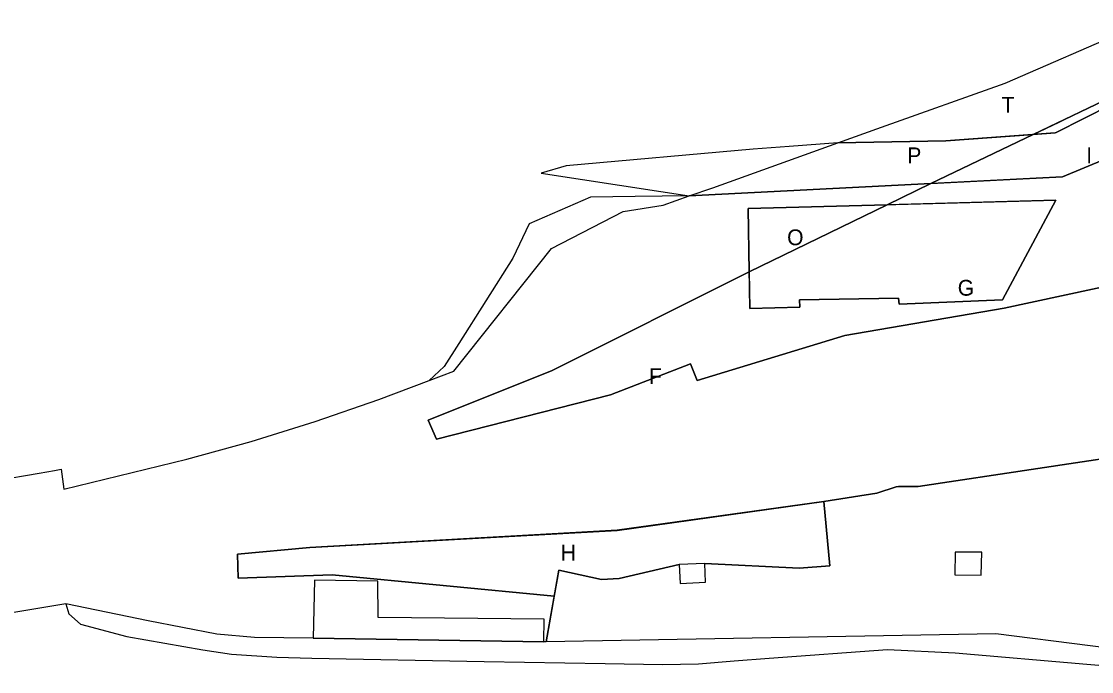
# Model space of a CAD drawing. Extents: x -749314 to -746497, y -1026537 to -1024935.
# Drawn here: x -748637.2 to -748467.6, y -1025353.9 to -1025250.8 of the extents above; entities that cross this region are included whole.
import ezdxf

# ---------------------------------------------------------------- set-up
doc = ezdxf.new("R2010")
doc.units = 0
for name, color, linetype in [('Default', 7, 'Continuous'), ('K_CD1', 7, 'Continuous'), ('K_JVL', 7, 'Continuous'), ('K_NH_SZDC', 7, 'Continuous'), ('K_SZDC1', 7, 'Continuous')]:
    doc.layers.add(name, color=color, linetype=linetype)

msp = doc.modelspace()

# ---------------------------------------------------------------- linework, layer by layer
at = {"layer": 'Default'}
for points in [[(-748507.76, -1025270.01), (-748500.87, -1025267.55), (-748481.26, -1025260.55), (-748461.55, -1025251.98), (-748456.49, -1025252.31), (-748455.09, -1025250.76), (-748454.67, -1025251.54), (-748454.2, -1025251.4), (-748452.63, -1025254.43), (-748451.72, -1025256.27), (-748463.12, -1025262.12), (-748476.84, -1025268.7), (-748490.67, -1025269.69)], [(-748531.33, -1025278.43), (-748527.62, -1025277.16), (-748507.76, -1025270.01), (-748490.67, -1025269.69), (-748476.84, -1025268.7), (-748493.03, -1025276.48)], [(-748522.01, -1025280.41), (-748499.95, -1025279.83), (-748521.85, -1025290.46)]]:
    msp.add_lwpolyline(points, close=True, dxfattribs=at)
for points in [[(-748641.22, -1025323.58), (-748634.38, -1025322.39), (-748631.94, -1025321.96), (-748630.88, -1025321.78), (-748630.45, -1025324.91), (-748610.99, -1025320.2), (-748600.75, -1025317.37), (-748590.64, -1025314.18), (-748580.51, -1025310.73), (-748572.57, -1025307.72), (-748568.67, -1025306.24), (-748553.15, -1025286.77), (-748541.82, -1025280.93), (-748535.47, -1025279.91), (-748531.33, -1025278.43), (-748493.03, -1025276.48), (-748499.95, -1025279.83), (-748522.01, -1025280.41), (-748521.85, -1025290.46), (-748553.04, -1025306.14), (-748572.73, -1025313.98), (-748571.38, -1025316.98), (-748543.82, -1025309.98), (-748531.16, -1025305.07), (-748530.09, -1025307.69), (-748506.7, -1025300.58), (-748481.42, -1025296.24), (-748425.39, -1025284.16)], [(-748457.11, -1025318.79), (-748495.05, -1025324.5), (-748498.15, -1025324.53), (-748498.52, -1025324.56), (-748501.59, -1025325.58), (-748509.99, -1025326.9), (-748542.75, -1025331.45), (-748591.49, -1025334.16), (-748602.92, -1025335.23), (-748602.82, -1025339.03), (-748587.95, -1025338.5), (-748552.74, -1025341.89), (-748554, -1025349.15), (-748554.4, -1025349.16), (-748554.35, -1025345.57), (-748580.64, -1025345.3), (-748580.67, -1025339.53), (-748590.73, -1025339.34), (-748590.92, -1025348.58), (-748600.23, -1025348.43), (-748606.2, -1025347.9), (-748617.1, -1025345.83), (-748630.15, -1025343.09), (-748640.31, -1025344.79)]]:
    msp.add_lwpolyline(points, dxfattribs=at)
at = {"layer": 'K_CD1'}
for points in [[(-748476.84, -1025268.7), (-748473.31, -1025268.45), (-748473.2, -1025268.39), (-748464.42, -1025263.92), (-748463.12, -1025262.12), (-748460.54, -1025262.55), (-748454.73, -1025263.51), (-748461.87, -1025271.11), (-748472.17, -1025275.42), (-748531.33, -1025278.43), (-748493.03, -1025276.48)], [(-748463.12, -1025262.12), (-748464.42, -1025263.92), (-748473.2, -1025268.39), (-748473.31, -1025268.45), (-748490.67, -1025269.69), (-748476.84, -1025268.7)], [(-748507.76, -1025270.01), (-748515.48, -1025270.58), (-748521.22, -1025271.01), (-748550.82, -1025273.68), (-748554.79, -1025274.83), (-748535.82, -1025277.74), (-748531.33, -1025278.43), (-748527.62, -1025277.16)], [(-748531.33, -1025278.43), (-748539.89, -1025278.54), (-748547, -1025278.63), (-748556.71, -1025282.88), (-748559.28, -1025288.32), (-748567.86, -1025301.84), (-748570.16, -1025305.46), (-748572.57, -1025307.72), (-748568.67, -1025306.24), (-748553.15, -1025286.77), (-748541.82, -1025280.93), (-748535.47, -1025279.91)], [(-748522.01, -1025280.41), (-748473.25, -1025279.13), (-748481.7, -1025294.92), (-748498.07, -1025295.61), (-748498.17, -1025294.62), (-748513.84, -1025294.91), (-748513.79, -1025296.06), (-748521.75, -1025296.26), (-748522.01, -1025280.41), (-748522.01, -1025280.41), (-748521.85, -1025290.46), (-748499.95, -1025279.83), (-748522.01, -1025280.41)], [(-748509.99, -1025326.9), (-748509.04, -1025337.08), (-748513.93, -1025337.44), (-748528.88, -1025336.7), (-748532.93, -1025336.89), (-748542.42, -1025339.12), (-748545.23, -1025339.23), (-748552.03, -1025337.79), (-748552.74, -1025341.89), (-748587.95, -1025338.5), (-748602.82, -1025339.03), (-748602.92, -1025335.23), (-748591.49, -1025334.16), (-748542.75, -1025331.45)], [(-748489.26, -1025338.51), (-748485.08, -1025338.56), (-748484.96, -1025334.94), (-748489.18, -1025334.92)], [(-748489.26, -1025338.51), (-748485.08, -1025338.56), (-748484.96, -1025334.94), (-748489.18, -1025334.92)], [(-748528.88, -1025336.7), (-748532.93, -1025336.89), (-748532.77, -1025339.9), (-748528.74, -1025339.7)]]:
    msp.add_lwpolyline(points, close=True, dxfattribs=at)
for points in [[(-748425.39, -1025284.16), (-748481.42, -1025296.24), (-748506.7, -1025300.58), (-748530.09, -1025307.69), (-748531.16, -1025305.07), (-748543.82, -1025309.98), (-748571.38, -1025316.98), (-748572.73, -1025313.98), (-748553.04, -1025306.14), (-748521.85, -1025290.46), (-748521.75, -1025296.26), (-748513.79, -1025296.06), (-748513.84, -1025294.91), (-748498.17, -1025294.62), (-748498.07, -1025295.61), (-748481.7, -1025294.92), (-748473.25, -1025279.13), (-748499.95, -1025279.83), (-748493.03, -1025276.48), (-748472.17, -1025275.42), (-748461.87, -1025271.11)], [(-748452.83, -1025351.66), (-748482.74, -1025347.88), (-748554, -1025349.15), (-748552.03, -1025337.79), (-748545.23, -1025339.23), (-748542.42, -1025339.12), (-748532.93, -1025336.89), (-748532.77, -1025339.9), (-748528.74, -1025339.7), (-748528.88, -1025336.7), (-748513.93, -1025337.44), (-748509.04, -1025337.08), (-748509.99, -1025326.9), (-748501.59, -1025325.58), (-748498.52, -1025324.56), (-748498.15, -1025324.53), (-748495.05, -1025324.5), (-748457.11, -1025318.79)]]:
    msp.add_lwpolyline(points, dxfattribs=at)
at = {"layer": 'K_JVL'}
msp.add_lwpolyline([(-748452.83, -1025351.66), (-748482.74, -1025347.88), (-748554, -1025349.15), (-748554.4, -1025349.16), (-748590.92, -1025348.58), (-748600.23, -1025348.43), (-748606.2, -1025347.9), (-748617.1, -1025345.83), (-748630.15, -1025343.09), (-748629.65, -1025344.68), (-748627.84, -1025346.36), (-748620.5, -1025348.31), (-748608.44, -1025350.39), (-748603.9, -1025351.07), (-748596.68, -1025351.56), (-748591.18, -1025351.73), (-748563.85, -1025352.25), (-748544.64, -1025352.57), (-748535.58, -1025352.72), (-748529.88, -1025352.61), (-748524.24, -1025352.17), (-748518.66, -1025351.74), (-748499.9, -1025350.36), (-748489.21, -1025350.86), (-748468.3, -1025352.69), (-748454.43, -1025353.86)], dxfattribs=at)
at = {"layer": 'K_NH_SZDC'}
for points in [[(-748476.84, -1025268.7), (-748472.72, -1025266.73), (-748471.99, -1025266.38), (-748463.12, -1025262.12), (-748451.72, -1025256.27), (-748452.63, -1025254.43)], [(-748493.03, -1025276.48), (-748476.84, -1025268.7)], [(-748499.95, -1025279.83), (-748493.03, -1025276.48)], [(-748521.85, -1025290.46), (-748553.04, -1025306.14), (-748572.73, -1025313.98), (-748571.38, -1025316.98), (-748543.82, -1025309.98), (-748531.16, -1025305.07), (-748530.09, -1025307.69), (-748506.7, -1025300.58), (-748481.42, -1025296.24), (-748425.39, -1025284.16), (-748398.16, -1025277.36)], [(-748521.85, -1025290.46), (-748499.95, -1025279.83)], [(-748552.74, -1025341.89), (-748562.14, -1025340.99), (-748587.95, -1025338.5), (-748602.82, -1025339.03), (-748602.92, -1025335.23), (-748591.49, -1025334.16), (-748542.77, -1025331.48), (-748509.99, -1025326.9)]]:
    msp.add_lwpolyline(points, dxfattribs=at)
at = {"layer": 'K_SZDC1'}
msp.add_lwpolyline([(-748554.4, -1025349.16), (-748554.35, -1025345.57), (-748580.64, -1025345.3), (-748580.67, -1025339.53), (-748590.73, -1025339.34), (-748590.92, -1025348.58)], close=True, dxfattribs=at)

# ---------------------------------------------------------------- texts
for s, p in [('T', (-748481.82, -1025265.25)), ('P', (-748496.78, -1025273.25)), ('I', (-748468.41, -1025273.25)), ('O', (-748515.82, -1025286.25)), ('G', (-748488.78, -1025294.25)), ('F', (-748537.72, -1025308.25)), ('H', (-748551.71, -1025336.25))]:
    msp.add_text(s, height=2.5).set_placement(p)

doc.saveas('drawing.dxf')
